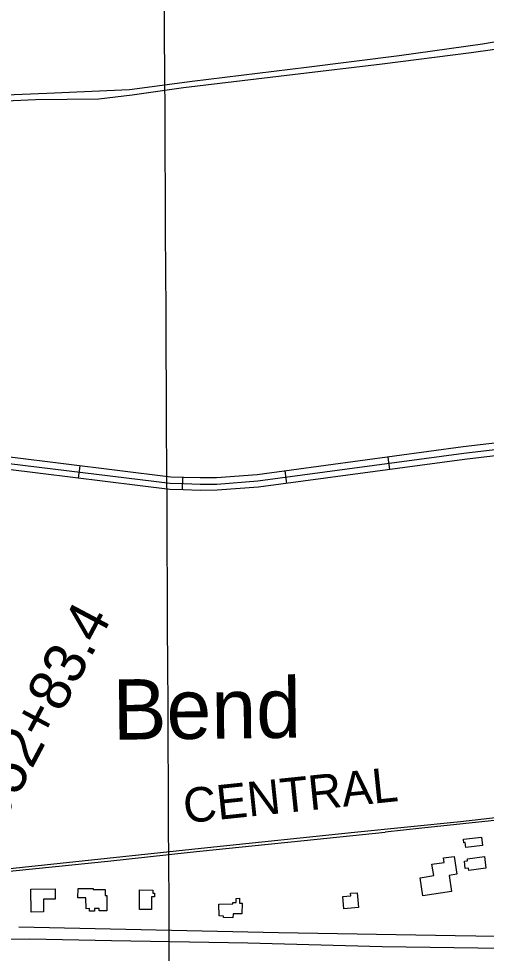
# Model space of a CAD drawing. Extents: x 3445503 to 3483459, y 540493 to 566012.
# Drawn here: x 3465075 to 3466200, y 553510 to 555755 of the extents above; entities that cross this region are included whole.
import ezdxf

# ---------------------------------------------------------------- set-up
doc = ezdxf.new("R2010")
doc.units = 0
for name, color, linetype in [('V-BLDG-OTLN', 7, 'Continuous'), ('V-DTCH-CNTR', 7, 'Continuous'), ('V-GRID-MAJR', 7, 'Continuous'), ('V-LEVE-TOET', 7, 'Continuous'), ('V-RAIL-IDEN', 7, 'Continuous'), ('V-RAIL-TRAK', 7, 'Continuous'), ('V-ROAD-CNTR', 7, 'Continuous'), ('V-SURV-IDEN', 7, 'Continuous'), ('V-TOPO-GNAM-IDEN', 7, 'Continuous'), ('V-TOPO-SHOR', 7, 'Continuous')]:
    doc.layers.add(name, color=color, linetype=linetype)

msp = doc.modelspace()

# ---------------------------------------------------------------- linework, layer by layer
at = {"layer": 'V-BLDG-OTLN'}
for points in [[(3466145.353, 553783.883), (3466188.756, 553789.003), (3466191.109, 553769.063), (3466150.545, 553764.3), (3466149.2090000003, 553775.746), (3466146.148, 553775.39)], [(3466116.441, 553658.443), (3466047.622, 553647.85), (3466040.929, 553691.35), (3466073.616, 553696.382), (3466069.421, 553723.647), (3466098.99, 553728.198), (3466097.358, 553738.741), (3466122.9790000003, 553742.675), (3466129.622, 553699.446), (3466110.84, 553696.556)], [(3466154.608, 553737.018), (3466195.404, 553742.3470000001), (3466199.066, 553714.331), (3466157.723, 553708.928), (3466157.063, 553714.042), (3466149.031, 553713.337), (3466147.595, 553731.4130000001), (3466154.901, 553732.103)], [(3465105.1, 553608.551), (3465104.506, 553663.639), (3465163.286, 553664.2710000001), (3465163.5500000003, 553639.9), (3465134.843, 553639.593), (3465135.167, 553609.6900000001)], [(3465218.145, 553665.054), (3465254.799, 553665.162), (3465254.811, 553663.21), (3465283.649, 553663.36), (3465283.724, 553648.971), (3465287.591, 553648.9890000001), (3465287.775, 553611.474), (3465269.042, 553611.382), (3465269.014, 553617.272), (3465257.973, 553617.2170000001), (3465258.002, 553610.952), (3465246.06, 553610.892), (3465246.029, 553616.9890000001), (3465237.372, 553616.946), (3465237.2430000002, 553643.204), (3465217.988, 553643.109)], [(3465366.232, 553661.93), (3465397.798, 553661.804), (3465397.933, 553653.949), (3465401.931, 553654.013), (3465402.054, 553645.559), (3465395.0840000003, 553645.569), (3465395.021, 553615.027), (3465366.1520000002, 553615.074)], [(3465557.323, 553599.376), (3465556.805, 553628.0160000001), (3465590.707, 553628.63), (3465590.654, 553631.587), (3465598.664, 553632.054), (3465598.242, 553641.784), (3465606.278, 553642.2660000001), (3465606.727, 553630.309), (3465612.9790000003, 553630.1680000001), (3465612.451, 553604.378), (3465591.2830000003, 553604.8470000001), (3465590.859, 553594.959), (3465567.758, 553595.868), (3465567.907, 553599.21)], [(3465889.861, 553655.068), (3465892.886, 553619.674), (3465857.799, 553616.682), (3465855.299, 553646.058), (3465874.282, 553647.678), (3465873.716, 553654.296)]]:
    msp.add_lwpolyline(points, close=True, dxfattribs=at)
at = {"layer": 'V-DTCH-CNTR'}
msp.add_lwpolyline([(3466325.821, 555717.35), (3466190.882, 555693.9130000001), (3465990.727, 555666.064), (3465767.855, 555637.827), (3465492.426, 555603.9180000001), (3465341.574, 555584.327), (3465142.988, 555574.984), (3464886.9590000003, 555564.822), (3464849.546, 555563.525), (3464641.312, 555556.312)], dxfattribs=at)
at = {"layer": 'V-GRID-MAJR'}
msp.add_spline([(3465476.125, 545965.8200000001), (3465445.288, 552023.321), (3465414.434, 558084.289), (3465383.579, 564145.273), (3465383.561, 564148.724)], degree=3, dxfattribs=at)
at = {"layer": 'V-LEVE-TOET'}
msp.add_lwpolyline([(3464658.224, 553486.218), (3464768.751, 553512.568), (3464858.486, 553529.095), (3464937.8340000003, 553537.787), (3465006.128, 553543.843), (3465102.417, 553544.775), (3465298.912, 553540.795), (3465626.836, 553534.6), (3465949.56, 553526.439), (3466237.791, 553522.079), (3466528.632, 553515.775), (3466792.791, 553511.343), (3466823.378, 553508.181)], dxfattribs=at)
at = {"layer": 'V-RAIL-TRAK'}
for points in [[(3467388.36, 553949.33), (3467251.541, 553935.633), (3467105.65, 553920.2880000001), (3466948.409, 553903.287), (3466712.708, 553879.248), (3466573.463, 553864.2710000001), (3466432.917, 553850.211), (3466242.6040000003, 553830.843), (3466045.161, 553810.482), (3465957.099, 553800.818)], [(3463647.612, 553562.609), (3463870.883, 553585.628), (3464013.461, 553600.957), (3464213.722, 553621.317), (3464400.375, 553640.017), (3464504.428, 553651.115), (3464583.788, 553659.031), (3464665.257, 553667.505), (3464705.627, 553671.706), (3464942.184, 553695.737), (3465116.522, 553713.751), (3465289.563, 553731.438), (3465488.203, 553752.765), (3465635.966, 553768.109), (3465761.699, 553780.796), (3465957.099, 553800.818)]]:
    msp.add_lwpolyline(points, dxfattribs=at)
at = {"layer": 'V-ROAD-CNTR'}
for p, q in [((3465968.3020254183, 554672.0886294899), (3465964.293033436, 554701.8195700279)), ((3465219.278523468, 554650.8916718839), (3465222.936516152, 554680.6676123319)), ((3465469.07702387, 554623.1587273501), (3465469.829022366, 554653.1496673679)), ((3465720.544520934, 554638.682696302), (3465716.5355289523, 554668.4136368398))]:
    msp.add_line(p, q, dxfattribs=at)
for points in [[(3463638.3496853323, 554878.8212160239), (3463987.29998743, 554832.6023084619), (3464280.552400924, 554794.5143846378), (3464371.643218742, 554780.144413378), (3464665.5096310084, 554731.0885114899), (3465052.138857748, 554686.5336006), (3465440.0010820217, 554638.8926958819), (3465471.7460185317, 554638.096697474), (3465512.085937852, 554636.930699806), (3465552.17185768, 554636.9556997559), (3465650.6256607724, 554644.390684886), (3466146.099669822, 554711.1975512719), (3466532.7968964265, 554756.6004604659), (3466917.007128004, 554810.084353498), (3467040.951880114, 554820.7023322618), (3467493.343975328, 554879.0952154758), (3467696.094569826, 554903.5841664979), (3467752.335457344, 554909.2991550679)], [(3466439.5670828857, 554760.757452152), (3466144.2226735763, 554726.0805215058), (3465649.057663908, 554659.314655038), (3465551.60185882, 554651.9556697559), (3465512.297937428, 554651.930669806), (3465472.151017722, 554653.0916674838), (3465441.106079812, 554653.869665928), (3465053.9118542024, 554701.4285708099), (3464766.036429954, 554734.6035044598)], [(3466444.176073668, 554731.092511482), (3466147.976666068, 554696.314581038), (3465652.193657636, 554629.4667147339), (3465552.7418565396, 554621.9557297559), (3465511.8739382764, 554621.930729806), (3465471.3410193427, 554623.101727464), (3465438.8960842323, 554623.9157258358), (3465050.365861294, 554671.6386303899), (3464663.414635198, 554716.2305412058), (3464641.042679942, 554719.965533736)], [(3462633.1446957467, 553462.7350482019), (3463482.4409971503, 553551.6268704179), (3464022.895916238, 553608.7357561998), (3464520.2349215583, 553660.05565356), (3464971.126019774, 553704.8295640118), (3465529.4559031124, 553763.5944464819), (3465882.8481963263, 553800.9443717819), (3466138.079685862, 553826.5673205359), (3466333.4622950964, 553848.816276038), (3466574.421813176, 553870.9202318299), (3467118.44872512, 553928.552116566), (3467570.959820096, 553977.4020188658), (3467901.9681580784, 554011.130951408), (3468263.5194349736, 554044.7658841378), (3468297.7413665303, 554048.5228766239)], [(3468377.857206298, 553507.4129588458), (3468138.2486855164, 553510.8579519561), (3467804.35235331, 553517.1789393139), (3467429.8341023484, 553528.2409171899), (3467045.091871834, 553536.311901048), (3466574.213813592, 553544.2598851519), (3466125.2957114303, 553551.527870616), (3465699.999562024, 553558.8528559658), (3465075.3838112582, 553572.5118286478)]]:
    msp.add_lwpolyline(points, dxfattribs=at)
at = {"layer": 'V-TOPO-SHOR'}
msp.add_lwpolyline([(3466443.396, 554752.167), (3466417.4050000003, 554957.487), (3466388.119, 555176.4720000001), (3466360.792, 555392.531), (3466333.771, 555616.73), (3466322.159, 555691.564), (3466320.85, 555693.188), (3466317.2660000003, 555694.478), (3466164.014, 555672.872), (3465949.906, 555645.877), (3465734.168, 555619.855), (3465472.222, 555588.49), (3465348.253, 555571.525), (3465268.205, 555561.852), (3465116.194, 555560.429), (3464865.91, 555548.954)], dxfattribs=at)

# ---------------------------------------------------------------- texts
at = {"layer": 'V-RAIL-IDEN'}
msp.add_text('CENTRAL', height=82.999832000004, rotation=5.93734988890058, dxfattribs=at).set_placement((3465475.523010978, 553822.0209202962))
at = {"layer": 'V-SURV-IDEN'}
msp.add_text('3952+83.4', height=100, rotation=62.10387230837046, dxfattribs=at).set_placement((3465002.5355064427, 553753.299557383))
at = {"layer": 'V-TOPO-GNAM-IDEN'}
msp.add_text('Bend', height=144.99971199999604, rotation=0.6418443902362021, dxfattribs=at).set_placement((3465302.269957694, 554022.714131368))

doc.saveas('drawing.dxf')
